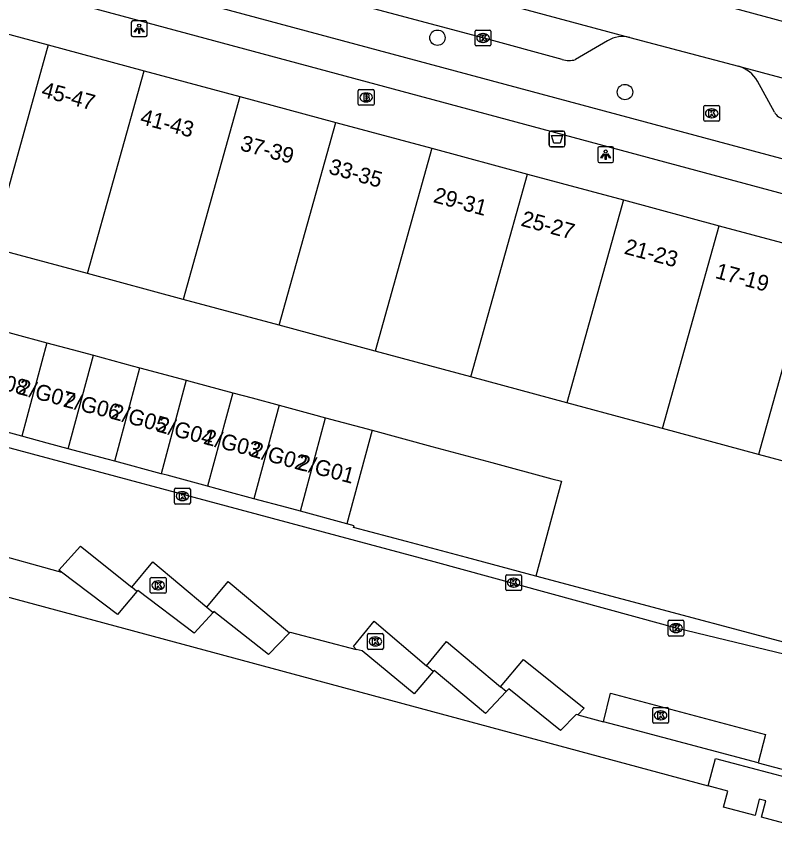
# Model space of a CAD drawing. Extents: x 160676 to 161153, y 383244 to 383713.
# Drawn here: x 160780.5 to 160828.6, y 383535.8 to 383587.8 of the extents above; entities that cross this region are included whole.
import ezdxf

# ---------------------------------------------------------------- set-up
doc = ezdxf.new("R2010")
doc.units = 0
for name, color, linetype in [('IMGEO_Afvalbak', 7, 'Continuous'), ('IMGEO_Boom', 7, 'Continuous'), ('IMGEO_Brandkraan', 7, 'Continuous'), ('IMGEO_Fietspad_gesloten', 7, 'Continuous'), ('IMGEO_Kolk', 7, 'Continuous'), ('IMGEO_Lichtpunt', 7, 'Continuous'), ('IMGEO_Pand', 7, 'Continuous'), ('IMGEO_Pand_nummerreeks', 7, 'Continuous'), ('IMGEO_Parkeervlak_open', 7, 'Continuous'), ('IMGEO_Rijbaan_lokaal_gesloten', 7, 'Continuous'), ('IMGEO_Rijbaan_lokaal_open', 7, 'Continuous'), ('IMGEO_Voetpad_open', 7, 'Continuous')]:
    doc.layers.add(name, color=color, linetype=linetype)

msp = doc.modelspace()

# ---------------------------------------------------------------- linework, layer by layer
at = {"layer": 'IMGEO_Afvalbak'}
for p, q in [((160814.275, 383579.646), (160814.275, 383580.446)), ((160814.275, 383580.446), (160814.275, 383579.646)), ((160814.375, 383580.546), (160815.165, 383580.546)), ((160815.165, 383580.546), (160814.375, 383580.546)), ((160815.265, 383580.446), (160815.265, 383579.646)), ((160815.265, 383579.646), (160815.265, 383580.446)), ((160815.165, 383579.546), (160814.375, 383579.546)), ((160814.375, 383579.546), (160815.165, 383579.546))]:
    msp.add_line(p, q, dxfattribs=at)
msp.add_lwpolyline([(160814.418, 383580.26), (160815.122, 383580.26), (160814.973, 383579.79), (160814.567, 383579.79), (160814.418, 383580.26)], dxfattribs=at)
for centre, start, end in [((160814.375, 383580.446), 90, 180), ((160814.375, 383580.446), 90, 180), ((160815.165, 383580.446), 0, 90), ((160815.165, 383580.446), 360, 90), ((160814.375, 383579.646), 180, 270), ((160814.375, 383579.646), 180, 270), ((160815.165, 383579.646), 270, 0), ((160815.165, 383579.646), 270, 0)]:
    msp.add_arc(centre, 0.1, start, end, dxfattribs=at)
at = {"layer": 'IMGEO_Boom'}
for centre in [(160807.18, 383586.475), (160819.082, 383583.023)]:
    msp.add_circle(centre, 0.489, dxfattribs=at)
at = {"layer": 'IMGEO_Brandkraan'}
for p, q in [((160802.155, 383582.259), (160802.155, 383583.111)), ((160802.23, 383583.185), (160803.082, 383583.185)), ((160802.643, 383582.965), (160802.668, 383582.965)), ((160803.156, 383583.111), (160803.156, 383582.259)), ((160802.666, 383582.405), (160802.641, 383582.405)), ((160803.082, 383582.185), (160802.23, 383582.185))]:
    msp.add_line(p, q, dxfattribs=at)
for points in [[(160802.155, 383582.259), (160802.155, 383583.111)], [(160802.23, 383583.185), (160803.082, 383583.185)], [(160802.503, 383582.885), (160802.503, 383582.485), (160802.716, 383582.485)], [(160802.734, 383582.885), (160802.503, 383582.885)], [(160802.682, 383582.804), (160802.628, 383582.804), (160802.628, 383582.728)], [(160803.156, 383583.111), (160803.156, 383582.259)], [(160802.628, 383582.728), (160802.681, 383582.728)], [(160802.69, 383582.652), (160802.628, 383582.652), (160802.628, 383582.571)], [(160802.628, 383582.571), (160802.69, 383582.571)], [(160803.082, 383582.185), (160802.23, 383582.185)]]:
    msp.add_lwpolyline(points, dxfattribs=at)
for centre, radius, start, end in [((160802.232, 383583.109), 0.0765, 91.552, 178.448), ((160802.232, 383583.109), 0.0765, 91.552, 178.448), ((160802.683, 383582.766), 0.0379, 267.8285, 90.9355), ((160802.738, 383582.74), 0.145, 59.4692, 91.5367), ((160802.763, 383582.787), 0.0922, 285.5137, 58.1501), ((160803.08, 383583.109), 0.0765, 1.552, 88.448), ((160803.08, 383583.109), 0.0765, 1.552, 88.448), ((160802.232, 383582.261), 0.0765, 181.552, 268.448), ((160802.232, 383582.261), 0.0765, 181.552, 268.448), ((160802.691, 383582.611), 0.0404, 269.8759, 90.5077), ((160802.722, 383582.736), 0.251, 268.6676, 293.5347), ((160802.768, 383582.595), 0.105, 301.3115, 78.989), ((160803.08, 383582.261), 0.0765, 271.552, 358.448), ((160803.08, 383582.261), 0.0765, 271.552, 358.448)]:
    msp.add_arc(centre, radius, start, end, dxfattribs=at)
for centre, major_axis, ratio, start_param, end_param in [((160802.642, 383582.685), (-0.387, 0.002), 0.722429, 4.712389, 7.853982), ((160802.667, 383582.685), (-0.39, 0.002), 0.717154, 1.570796, 4.712389)]:
    msp.add_ellipse(centre, major_axis=major_axis, ratio=ratio, start_param=start_param, end_param=end_param, dxfattribs=at)
at = {"layer": 'IMGEO_Fietspad_gesloten'}
for points in [[(160904.417, 383556.04), (160869.912, 383565.633), (160851.652, 383570.489), (160741.54, 383600.127)], [(160753.356, 383599.164), (160754.374, 383598.874), (160872.54, 383567.128), (160873.601, 383566.834)]]:
    msp.add_lwpolyline(points, dxfattribs=at)
at = {"layer": 'IMGEO_Kolk'}
for p, q in [((160809.647, 383586.958), (160810.499, 383586.958)), ((160809.572, 383586.032), (160809.572, 383586.884)), ((160810.06, 383586.738), (160810.085, 383586.738)), ((160810.573, 383586.884), (160810.573, 383586.032)), ((160810.499, 383585.958), (160809.647, 383585.958)), ((160810.083, 383586.178), (160810.058, 383586.178)), ((160824.087, 383581.25), (160824.087, 383582.102)), ((160824.162, 383582.176), (160825.014, 383582.176)), ((160824.575, 383581.956), (160824.6, 383581.956)), ((160825.088, 383582.102), (160825.088, 383581.25)), ((160824.598, 383581.396), (160824.573, 383581.396)), ((160825.014, 383581.176), (160824.162, 383581.176)), ((160790.571, 383557.878), (160791.423, 383557.878)), ((160790.496, 383556.952), (160790.496, 383557.804)), ((160790.984, 383557.658), (160791.009, 383557.658)), ((160791.497, 383557.804), (160791.497, 383556.952)), ((160791.423, 383556.878), (160790.571, 383556.878)), ((160791.007, 383557.098), (160790.982, 383557.098)), ((160788.957, 383551.294), (160788.957, 383552.146)), ((160789.032, 383552.22), (160789.884, 383552.22)), ((160789.958, 383552.146), (160789.958, 383551.294)), ((160811.514, 383551.462), (160811.514, 383552.314)), ((160811.589, 383552.388), (160812.441, 383552.388)), ((160812.002, 383552.168), (160812.027, 383552.168)), ((160812.515, 383552.314), (160812.515, 383551.462)), ((160789.445, 383552), (160789.47, 383552)), ((160812.025, 383551.608), (160812, 383551.608)), ((160789.884, 383551.22), (160789.032, 383551.22)), ((160789.468, 383551.44), (160789.443, 383551.44)), ((160812.441, 383551.388), (160811.589, 383551.388)), ((160821.9, 383549.502), (160822.752, 383549.502)), ((160821.825, 383548.576), (160821.825, 383549.428)), ((160822.313, 383549.282), (160822.338, 383549.282)), ((160822.826, 383549.428), (160822.826, 383548.576)), ((160802.745, 383547.728), (160802.745, 383548.58)), ((160802.82, 383548.654), (160803.672, 383548.654)), ((160803.746, 383548.58), (160803.746, 383547.728)), ((160822.752, 383548.502), (160821.9, 383548.502)), ((160822.336, 383548.722), (160822.311, 383548.722)), ((160803.233, 383548.434), (160803.258, 383548.434)), ((160803.672, 383547.654), (160802.82, 383547.654)), ((160803.256, 383547.874), (160803.231, 383547.874)), ((160820.845, 383543.044), (160820.845, 383543.896)), ((160820.92, 383543.97), (160821.772, 383543.97)), ((160821.846, 383543.896), (160821.846, 383543.044)), ((160821.333, 383543.75), (160821.358, 383543.75)), ((160821.772, 383542.97), (160820.92, 383542.97)), ((160821.356, 383543.19), (160821.331, 383543.19))]:
    msp.add_line(p, q, dxfattribs=at)
for points in [[(160809.647, 383586.958), (160810.499, 383586.958)], [(160809.572, 383586.032), (160809.572, 383586.884)], [(160809.893, 383586.658), (160810.016, 383586.658), (160810.016, 383586.507), (160810.146, 383586.658), (160810.31, 383586.658), (160810.164, 383586.507), (160810.317, 383586.258), (160810.165, 383586.258), (160810.08, 383586.422), (160810.016, 383586.355), (160810.016, 383586.258), (160809.893, 383586.258), (160809.893, 383586.658)], [(160810.573, 383586.884), (160810.573, 383586.032)], [(160810.499, 383585.958), (160809.647, 383585.958)], [(160824.087, 383581.25), (160824.087, 383582.102)], [(160824.162, 383582.176), (160825.014, 383582.176)], [(160824.408, 383581.876), (160824.531, 383581.876), (160824.531, 383581.725), (160824.661, 383581.876), (160824.825, 383581.876), (160824.679, 383581.725), (160824.832, 383581.476), (160824.68, 383581.476), (160824.595, 383581.64), (160824.531, 383581.573), (160824.531, 383581.476), (160824.408, 383581.476), (160824.408, 383581.876)], [(160825.088, 383582.102), (160825.088, 383581.25)], [(160825.014, 383581.176), (160824.162, 383581.176)], [(160790.571, 383557.878), (160791.423, 383557.878)], [(160790.496, 383556.952), (160790.496, 383557.804)], [(160790.817, 383557.578), (160790.94, 383557.578), (160790.94, 383557.427), (160791.07, 383557.578), (160791.234, 383557.578), (160791.088, 383557.427), (160791.241, 383557.178), (160791.089, 383557.178), (160791.004, 383557.342), (160790.94, 383557.275), (160790.94, 383557.178), (160790.817, 383557.178), (160790.817, 383557.578)], [(160791.497, 383557.804), (160791.497, 383556.952)], [(160791.423, 383556.878), (160790.571, 383556.878)], [(160788.957, 383551.294), (160788.957, 383552.146)], [(160789.032, 383552.22), (160789.884, 383552.22)], [(160789.958, 383552.146), (160789.958, 383551.294)], [(160811.514, 383551.462), (160811.514, 383552.314)], [(160811.589, 383552.388), (160812.441, 383552.388)], [(160811.835, 383552.088), (160811.958, 383552.088), (160811.958, 383551.937), (160812.088, 383552.088), (160812.252, 383552.088), (160812.106, 383551.937), (160812.259, 383551.688), (160812.107, 383551.688), (160812.022, 383551.852), (160811.958, 383551.785), (160811.958, 383551.688), (160811.835, 383551.688), (160811.835, 383552.088)], [(160812.515, 383552.314), (160812.515, 383551.462)], [(160789.278, 383551.92), (160789.401, 383551.92), (160789.401, 383551.769), (160789.531, 383551.92), (160789.695, 383551.92), (160789.549, 383551.769), (160789.702, 383551.52), (160789.55, 383551.52), (160789.465, 383551.684), (160789.401, 383551.617), (160789.401, 383551.52), (160789.278, 383551.52), (160789.278, 383551.92)], [(160789.884, 383551.22), (160789.032, 383551.22)], [(160812.441, 383551.388), (160811.589, 383551.388)], [(160821.9, 383549.502), (160822.752, 383549.502)], [(160821.825, 383548.576), (160821.825, 383549.428)], [(160822.146, 383549.202), (160822.269, 383549.202), (160822.269, 383549.051), (160822.399, 383549.202), (160822.563, 383549.202), (160822.417, 383549.051), (160822.57, 383548.802), (160822.418, 383548.802), (160822.333, 383548.966), (160822.269, 383548.899), (160822.269, 383548.802), (160822.146, 383548.802), (160822.146, 383549.202)], [(160822.826, 383549.428), (160822.826, 383548.576)], [(160802.745, 383547.728), (160802.745, 383548.58)], [(160802.82, 383548.654), (160803.672, 383548.654)], [(160803.746, 383548.58), (160803.746, 383547.728)], [(160822.752, 383548.502), (160821.9, 383548.502)], [(160803.066, 383548.354), (160803.189, 383548.354), (160803.189, 383548.203), (160803.319, 383548.354), (160803.483, 383548.354), (160803.337, 383548.203), (160803.49, 383547.954), (160803.338, 383547.954), (160803.253, 383548.118), (160803.189, 383548.051), (160803.189, 383547.954), (160803.066, 383547.954), (160803.066, 383548.354)], [(160803.672, 383547.654), (160802.82, 383547.654)], [(160820.845, 383543.044), (160820.845, 383543.896)], [(160820.92, 383543.97), (160821.772, 383543.97)], [(160821.846, 383543.896), (160821.846, 383543.044)], [(160821.166, 383543.67), (160821.289, 383543.67), (160821.289, 383543.519), (160821.419, 383543.67), (160821.583, 383543.67), (160821.437, 383543.519), (160821.59, 383543.27), (160821.438, 383543.27), (160821.353, 383543.434), (160821.289, 383543.367), (160821.289, 383543.27), (160821.166, 383543.27), (160821.166, 383543.67)], [(160821.772, 383542.97), (160820.92, 383542.97)]]:
    msp.add_lwpolyline(points, dxfattribs=at)
for centre, start, end in [((160809.649, 383586.882), 91.552, 178.448), ((160809.649, 383586.882), 91.552, 178.448), ((160810.497, 383586.882), 1.552, 88.448), ((160810.497, 383586.882), 1.552, 88.448), ((160809.649, 383586.034), 181.552, 268.448), ((160809.649, 383586.034), 181.552, 268.448), ((160810.497, 383586.034), 271.552, 358.448), ((160810.497, 383586.034), 271.552, 358.448), ((160824.164, 383582.1), 91.552, 178.448), ((160824.164, 383582.1), 91.552, 178.448), ((160825.012, 383582.1), 1.552, 88.448), ((160825.012, 383582.1), 1.552, 88.448), ((160824.164, 383581.252), 181.552, 268.448), ((160824.164, 383581.252), 181.552, 268.448), ((160825.012, 383581.252), 271.552, 358.448), ((160825.012, 383581.252), 271.552, 358.448), ((160790.573, 383557.802), 91.552, 178.448), ((160790.573, 383557.802), 91.552, 178.448), ((160791.421, 383557.802), 1.552, 88.448), ((160791.421, 383557.802), 1.552, 88.448), ((160790.573, 383556.954), 181.552, 268.448), ((160790.573, 383556.954), 181.552, 268.448), ((160791.421, 383556.954), 271.552, 358.448), ((160791.421, 383556.954), 271.552, 358.448), ((160789.034, 383552.144), 91.552, 178.448), ((160789.034, 383552.144), 91.552, 178.448), ((160789.882, 383552.144), 1.552, 88.448), ((160789.882, 383552.144), 1.552, 88.448), ((160811.591, 383552.312), 91.552, 178.448), ((160811.591, 383552.312), 91.552, 178.448), ((160812.439, 383552.312), 1.552, 88.448), ((160812.439, 383552.312), 1.552, 88.448), ((160789.034, 383551.296), 181.552, 268.448), ((160789.034, 383551.296), 181.552, 268.448), ((160789.882, 383551.296), 271.552, 358.448), ((160789.882, 383551.296), 271.552, 358.448), ((160811.591, 383551.464), 181.552, 268.448), ((160811.591, 383551.464), 181.552, 268.448), ((160812.439, 383551.464), 271.552, 358.448), ((160812.439, 383551.464), 271.552, 358.448), ((160821.902, 383549.426), 91.552, 178.448), ((160821.902, 383549.426), 91.552, 178.448), ((160822.75, 383549.426), 1.552, 88.448), ((160822.75, 383549.426), 1.552, 88.448), ((160802.822, 383548.578), 91.552, 178.448), ((160802.822, 383548.578), 91.552, 178.448), ((160803.67, 383548.578), 1.552, 88.448), ((160803.67, 383548.578), 1.552, 88.448), ((160821.902, 383548.578), 181.552, 268.448), ((160821.902, 383548.578), 181.552, 268.448), ((160822.75, 383548.578), 271.552, 358.448), ((160822.75, 383548.578), 271.552, 358.448), ((160802.822, 383547.73), 181.552, 268.448), ((160802.822, 383547.73), 181.552, 268.448), ((160803.67, 383547.73), 271.552, 358.448), ((160803.67, 383547.73), 271.552, 358.448), ((160820.922, 383543.894), 91.552, 178.448), ((160820.922, 383543.894), 91.552, 178.448), ((160821.77, 383543.894), 1.552, 88.448), ((160821.77, 383543.894), 1.552, 88.448), ((160820.922, 383543.046), 181.552, 268.448), ((160820.922, 383543.046), 181.552, 268.448), ((160821.77, 383543.046), 271.552, 358.448), ((160821.77, 383543.046), 271.552, 358.448)]:
    msp.add_arc(centre, 0.0765, start, end, dxfattribs=at)
for centre, major_axis, ratio, start_param, end_param in [((160810.059, 383586.458), (-0.387, 0.002), 0.722429, 4.712389, 7.853982), ((160810.084, 383586.458), (-0.39, 0.002), 0.717154, 1.570796, 4.712389), ((160824.574, 383581.676), (-0.387, 0.002), 0.722429, 4.712389, 7.853982), ((160824.599, 383581.676), (-0.39, 0.002), 0.717154, 1.570796, 4.712389), ((160790.983, 383557.378), (-0.387, 0.002), 0.722429, 4.712389, 7.853982), ((160791.008, 383557.378), (-0.39, 0.002), 0.717154, 1.570796, 4.712389), ((160812.001, 383551.888), (-0.387, 0.002), 0.722429, 4.712389, 7.853982), ((160812.026, 383551.888), (-0.39, 0.002), 0.717154, 1.570796, 4.712389), ((160789.444, 383551.72), (-0.387, 0.002), 0.722429, 4.712389, 7.853982), ((160789.469, 383551.72), (-0.39, 0.002), 0.717154, 1.570796, 4.712389), ((160822.312, 383549.002), (-0.387, 0.002), 0.722429, 4.712389, 7.853982), ((160822.337, 383549.002), (-0.39, 0.002), 0.717154, 1.570796, 4.712389), ((160803.232, 383548.154), (-0.387, 0.002), 0.722429, 4.712389, 7.853982), ((160803.257, 383548.154), (-0.39, 0.002), 0.717154, 1.570796, 4.712389), ((160821.332, 383543.47), (-0.387, 0.002), 0.722429, 4.712389, 7.853982), ((160821.357, 383543.47), (-0.39, 0.002), 0.717154, 1.570796, 4.712389)]:
    msp.add_ellipse(centre, major_axis=major_axis, ratio=ratio, start_param=start_param, end_param=end_param, dxfattribs=at)
at = {"layer": 'IMGEO_Lichtpunt'}
for p, q in [((160787.752, 383587.445), (160787.752, 383586.638)), ((160787.752, 383587.445), (160787.752, 383586.638)), ((160788.654, 383587.54), (160787.846, 383587.54)), ((160788.654, 383587.54), (160787.846, 383587.54)), ((160788.748, 383586.638), (160788.748, 383587.445)), ((160788.748, 383586.638), (160788.748, 383587.445)), ((160787.846, 383586.544), (160788.654, 383586.544)), ((160787.846, 383586.544), (160788.654, 383586.544)), ((160817.358, 383579.457), (160817.358, 383578.65)), ((160817.358, 383579.457), (160817.358, 383578.65)), ((160818.26, 383579.552), (160817.452, 383579.552)), ((160818.26, 383579.552), (160817.452, 383579.552)), ((160818.354, 383578.65), (160818.354, 383579.457)), ((160818.354, 383578.65), (160818.354, 383579.457)), ((160817.452, 383578.556), (160818.26, 383578.556)), ((160817.452, 383578.556), (160818.26, 383578.556))]:
    msp.add_line(p, q, dxfattribs=at)
for points in [[(160788.126, 383587.109), (160788.165, 383587.081), (160787.977, 383586.819), (160787.939, 383586.846), (160788.126, 383587.109)], [(160788.228, 383587.061), (160788.275, 383587.061), (160788.275, 383586.739), (160788.228, 383586.739), (160788.228, 383587.061)], [(160788.338, 383587.081), (160788.376, 383587.108), (160788.563, 383586.846), (160788.524, 383586.818), (160788.338, 383587.081)], [(160817.732, 383579.121), (160817.771, 383579.093), (160817.583, 383578.831), (160817.545, 383578.858), (160817.732, 383579.121)], [(160817.834, 383579.073), (160817.881, 383579.073), (160817.881, 383578.751), (160817.834, 383578.751), (160817.834, 383579.073)], [(160817.944, 383579.093), (160817.982, 383579.12), (160818.169, 383578.858), (160818.13, 383578.83), (160817.944, 383579.093)]]:
    msp.add_lwpolyline(points, dxfattribs=at)
for centre in [(160788.251, 383587.243), (160817.857, 383579.255)]:
    msp.add_circle(centre, 0.0994, dxfattribs=at)
for centre, start, end in [((160787.846, 383587.445), 90, 180), ((160787.846, 383587.445), 90, 180), ((160788.654, 383587.445), 0, 90), ((160788.654, 383587.445), 0, 90), ((160787.846, 383586.638), 180, 270), ((160787.846, 383586.638), 180, 270), ((160788.654, 383586.638), 270, 0), ((160788.654, 383586.638), 270, 360), ((160817.452, 383579.457), 90, 180), ((160817.452, 383579.457), 90, 180), ((160818.26, 383579.457), 0, 90), ((160818.26, 383579.457), 0, 90), ((160817.452, 383578.65), 180, 270), ((160817.452, 383578.65), 180, 270), ((160818.26, 383578.65), 270, 0), ((160818.26, 383578.65), 270, 360)]:
    msp.add_arc(centre, 0.0946, start, end, dxfattribs=at)
at = {"layer": 'IMGEO_Pand'}
for points in [[(160776.398, 383587.651), (160782.481, 383586.013)], [(160782.481, 383586.013), (160778.885, 383573.14)], [(160782.481, 383586.013), (160788.565, 383584.374)], [(160784.969, 383571.501), (160788.565, 383584.374)], [(160788.565, 383584.374), (160794.648, 383582.735)], [(160794.648, 383582.735), (160791.052, 383569.862)], [(160794.648, 383582.735), (160800.731, 383581.097)], [(160797.136, 383568.224), (160800.731, 383581.097)], [(160800.731, 383581.097), (160806.815, 383579.458)], [(160806.815, 383579.458), (160803.219, 383566.585)], [(160806.815, 383579.458), (160812.898, 383577.819)], [(160809.303, 383564.947), (160812.898, 383577.819)], [(160812.898, 383577.819), (160818.982, 383576.181)], [(160818.982, 383576.181), (160815.386, 383563.308)], [(160818.982, 383576.181), (160825.065, 383574.542)], [(160821.47, 383561.669), (160825.065, 383574.542)], [(160825.065, 383574.542), (160831.149, 383572.903)], [(160784.969, 383571.501), (160778.885, 383573.14)], [(160831.149, 383572.903), (160827.553, 383560.031)], [(160791.052, 383569.862), (160784.969, 383571.501)], [(160797.136, 383568.224), (160791.052, 383569.862)], [(160803.219, 383566.585), (160797.136, 383568.224)], [(160779.452, 383567.911), (160780.202, 383567.709), (160782.399, 383567.117)], [(160782.399, 383567.117), (160780.801, 383561.184)], [(160782.399, 383567.117), (160784.006, 383566.684), (160785.346, 383566.323)], [(160783.748, 383560.389), (160785.346, 383566.323)], [(160785.346, 383566.323), (160787.811, 383565.659), (160788.293, 383565.529)], [(160809.303, 383564.947), (160803.219, 383566.585)], [(160786.695, 383559.595), (160788.293, 383565.529)], [(160788.293, 383565.529), (160791.24, 383564.736)], [(160791.24, 383564.736), (160789.642, 383558.801)], [(160791.24, 383564.736), (160791.615, 383564.635), (160794.187, 383563.942)], [(160815.386, 383563.308), (160809.303, 383564.947)], [(160794.187, 383563.942), (160792.589, 383558.007)], [(160794.187, 383563.942), (160795.419, 383563.61), (160797.134, 383563.148)], [(160797.134, 383563.148), (160795.536, 383557.213)], [(160797.134, 383563.148), (160799.224, 383562.585), (160800.081, 383562.354)], [(160821.47, 383561.669), (160819.477, 383562.206), (160815.386, 383563.308)], [(160780.801, 383561.184), (160778.604, 383561.776), (160777.854, 383561.978)], [(160798.482, 383556.419), (160800.081, 383562.354)], [(160800.081, 383562.354), (160803.028, 383561.56)], [(160803.028, 383561.56), (160801.429, 383555.625)], [(160803.028, 383561.56), (160806.833, 383560.536), (160810.637, 383559.511), (160814.441, 383558.486), (160815.054, 383558.321), (160813.434, 383552.307)], [(160827.553, 383560.031), (160821.47, 383561.669)], [(160783.748, 383560.389), (160782.408, 383560.751), (160780.801, 383561.184)], [(160786.695, 383559.595), (160786.212, 383559.725), (160783.748, 383560.389)], [(160833.637, 383558.393), (160827.553, 383560.031)], [(160789.642, 383558.801), (160786.695, 383559.595)], [(160792.589, 383558.007), (160790.016, 383558.7), (160789.642, 383558.801)], [(160795.536, 383557.213), (160793.821, 383557.675), (160792.589, 383558.007)], [(160798.482, 383556.419), (160797.625, 383556.65), (160795.536, 383557.213)], [(160801.429, 383555.625), (160798.482, 383556.419)], [(160813.434, 383552.307), (160809.014, 383553.486), (160805.207, 383554.502), (160801.862, 383555.394), (160801.89, 383555.501), (160801.429, 383555.625)], [(160772.161, 383553.067), (160824.365, 383538.998)], [(160833.395, 383536.594), (160832.418, 383536.856), (160832.143, 383535.833), (160830.138, 383536.367), (160830.422, 383537.388), (160830.007, 383537.504), (160829.722, 383536.483), (160827.746, 383537.005), (160828.012, 383538.031), (160827.604, 383538.137), (160827.337, 383537.111), (160825.342, 383537.638), (160825.617, 383538.662), (160824.365, 383538.998)]]:
    msp.add_lwpolyline(points, dxfattribs=at)
at = {"layer": 'IMGEO_Parkeervlak_open'}
for points in [[(160815.088, 383585.095), (160810.069, 383586.459), (160795.367, 383590.393)], [(160817.978, 383586.286), (160815.949, 383585.082)], [(160828.563, 383581.758), (160827.487, 383583.708)], [(160788.11, 383551.327), (160787.775, 383551.597)], [(160792.542, 383550.339), (160792.94, 383550.004)], [(160806.916, 383546.239), (160806.478, 383546.613)], [(160811.537, 383544.97), (160811.172, 383545.277)]]:
    msp.add_lwpolyline(points, dxfattribs=at)
for centre, radius, start, end in [((160818.946, 383584.63), 1.918, 76.7407, 120.3049), ((160815.542, 383586.616), 1.587, 253.3984, 284.8716), ((160825.752, 383582.763), 1.976, 28.5683, 74.4951), ((160829.416, 383582.254), 0.987, 210.1675, 256.3296)]:
    msp.add_arc(centre, radius, start, end, dxfattribs=at)
at = {"layer": 'IMGEO_Rijbaan_lokaal_gesloten'}
for points in [[(160913.282, 383564.496), (160869.874, 383576.512), (160797.171, 383596.125)], [(160792.524, 383593.731), (160819.386, 383586.497)], [(160819.386, 383586.497), (160826.28, 383584.667)], [(160826.28, 383584.667), (160844.949, 383579.673)]]:
    msp.add_lwpolyline(points, dxfattribs=at)
at = {"layer": 'IMGEO_Rijbaan_lokaal_open'}
for points in [[(160850.083, 383542.287), (160822.326, 383549.002), (160821.426, 383549.252), (160806.97, 383553.205), (160770.322, 383563.034), (160748.417, 383568.908), (160742.099, 383570.623), (160736.61, 383572.879)], [(160783.322, 383552.547), (160783.154, 383552.689), (160784.524, 383554.209), (160787.775, 383551.597)], [(160778.768, 383553.77), (160778.807, 383553.809), (160783.095, 383552.611), (160783.322, 383552.547)], [(160787.775, 383551.597), (160789.123, 383553.211), (160792.542, 383550.339)], [(160792.542, 383550.339), (160793.905, 383551.971), (160797.791, 383548.706)], [(160802.032, 383547.656), (160801.852, 383547.834), (160803.172, 383549.44), (160806.478, 383546.613)], [(160797.791, 383548.706), (160797.831, 383548.748), (160802.032, 383547.656)], [(160806.478, 383546.613), (160807.757, 383548.146), (160811.172, 383545.277)], [(160811.172, 383545.277), (160812.635, 383547.01), (160816.499, 383543.92), (160816.082, 383543.49)], [(160817.716, 383543.056), (160818.163, 383544.869), (160828.009, 383542.256), (160827.531, 383540.452)], [(160816.082, 383543.49), (160817.716, 383543.056)], [(160827.531, 383540.452), (160830.643, 383539.626), (160831.364, 383539.424)]]:
    msp.add_lwpolyline(points, dxfattribs=at)
at = {"layer": 'IMGEO_Voetpad_open'}
for points in [[(160788.11, 383551.327), (160786.884, 383549.861), (160783.322, 383552.547)], [(160835.773, 383546.777), (160835.666, 383546.367), (160813.434, 383552.307)], [(160792.94, 383550.004), (160791.74, 383548.675), (160788.159, 383551.385), (160788.11, 383551.327)], [(160797.791, 383548.706), (160796.452, 383547.324), (160792.987, 383550.057), (160792.94, 383550.004)], [(160806.916, 383546.239), (160805.699, 383544.831), (160802.399, 383547.561), (160802.032, 383547.656)], [(160811.537, 383544.97), (160810.235, 383543.592), (160806.981, 383546.315), (160806.916, 383546.239)], [(160816.082, 383543.49), (160815.994, 383543.513), (160814.986, 383542.501), (160811.702, 383545.144), (160811.537, 383544.97)], [(160827.531, 383540.452), (160819.812, 383542.5), (160817.716, 383543.056)], [(160824.365, 383538.998), (160824.823, 383540.726), (160833.805, 383538.352), (160833.395, 383536.594)]]:
    msp.add_lwpolyline(points, dxfattribs=at)

# ---------------------------------------------------------------- texts
at = {"layer": 'IMGEO_Pand_nummerreeks'}
for s, rotation, p in [('45-47', 344.8828, (160781.984, 383582.742)), ('41-43', 345.0686, (160788.254, 383581.013)), ('37-39', 344.9787, (160794.605, 383579.345)), ('33-35', 344.3072, (160800.215, 383577.868)), ('29-31', 344.9431, (160806.862, 383576.048)), ('25-27', 344.8828, (160812.424, 383574.551)), ('21-23', 345.1206, (160818.977, 383572.774)), ('17-19', 344.9315, (160824.756, 383571.233)), ('2/G08', 345.2204, (160777.504, 383564.669)), ('2/G07', 344.7753, (160780.49, 383563.879)), ('2/G06', 345.8741, (160783.374, 383563.074)), ('2/G05', 344.7753, (160786.394, 383562.311)), ('2/G04', 345.0243, (160789.309, 383561.494)), ('2/G03', 345.3232, (160792.278, 383560.709)), ('2/G02', 344.3289, (160795.249, 383559.921)), ('2/G01', 345.1283, (160798.231, 383559.096))]:
    msp.add_text(s, height=1, rotation=rotation, dxfattribs=at).set_placement(p)

doc.saveas('drawing.dxf')
